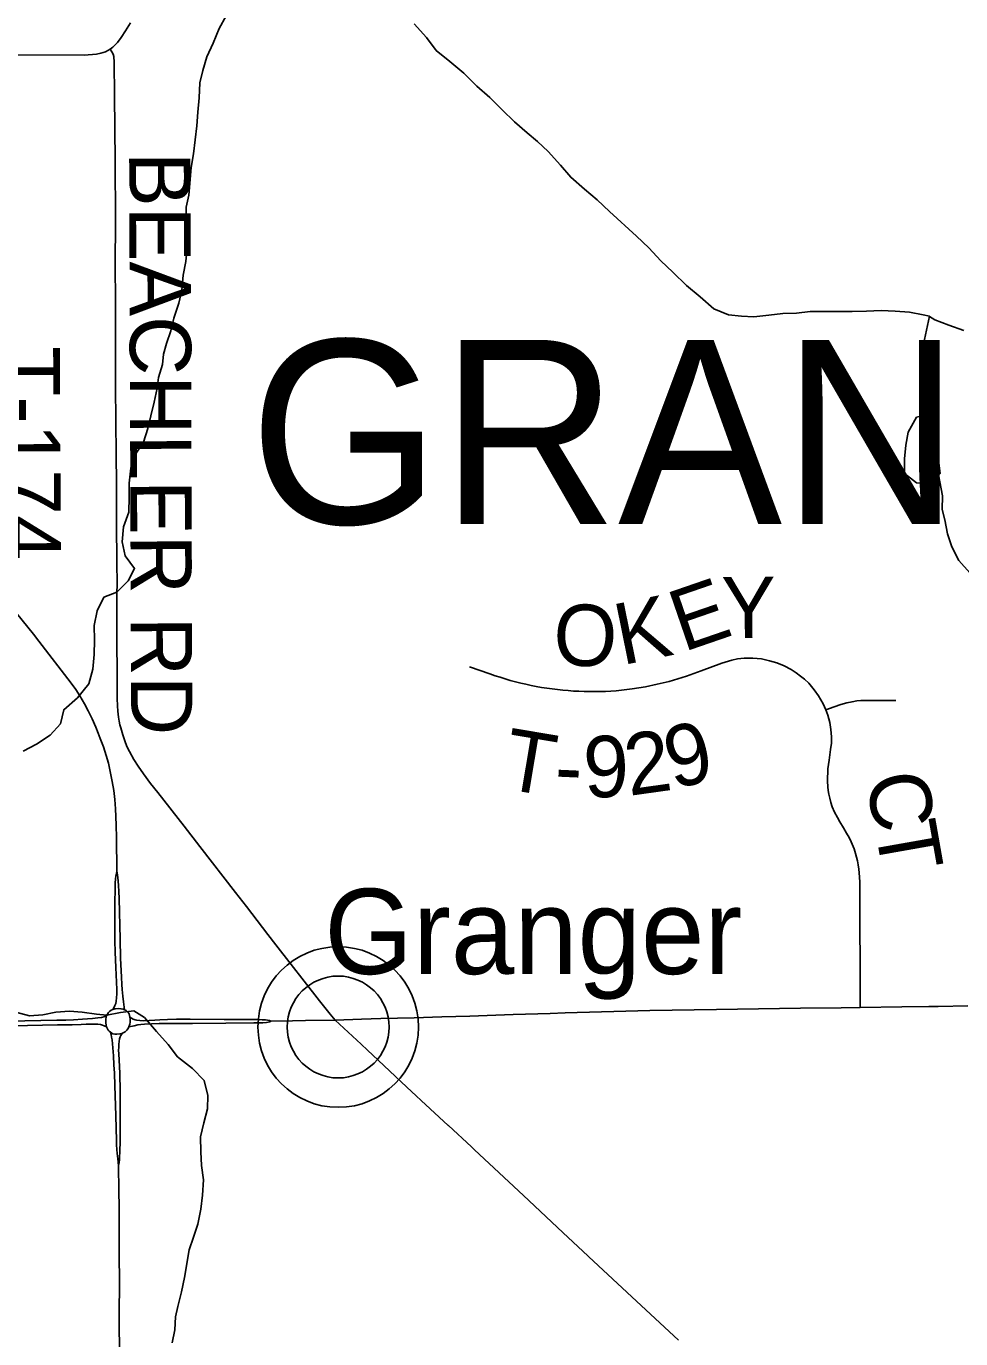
# Model space of a CAD drawing. Extents: x 0 to 34, y 0 to 22.
# Drawn here: x 5.327 to 6.193, y 15.589 to 16.805 of the extents above; entities that cross this region are included whole.
import ezdxf

# ---------------------------------------------------------------- set-up
doc = ezdxf.new("R2010")
doc.units = 0
for name, color, linetype in [('GM_X_County_Road', 7, 'Continuous'), ('GM_X_Minor_Lake', 7, 'Continuous'), ('GM_X_Minor_River', 7, 'Continuous'), ('GM_X_State_Route', 7, 'Continuous'), ('GM_X_Township_Road', 7, 'Continuous'), ('GM_X_Township_Road_Text', 7, 'Continuous'), ('GM_X_Township_Text', 7, 'Continuous'), ('GM_X_Unincorporated', 7, 'Continuous'), ('GM_X_Unincorporated_Location', 7, 'Continuous'), ('GM_X_Unincorporated_Text', 7, 'Continuous')]:
    doc.layers.add(name, color=color, linetype=linetype)

msp = doc.modelspace()

# ---------------------------------------------------------------- linework, layer by layer
at = {"layer": 'GM_X_County_Road'}
msp.add_line((5.5539, 15.8835), (5.574, 15.8838), dxfattribs=at)
for points in [[(5.4073, 15.8944), (5.4095, 15.895), (5.4122, 15.8952), (5.4149, 15.895), (5.4169, 15.8946), (5.4182, 15.8941)], [(5.574, 15.8838), (5.586, 15.884), (5.6136, 15.8845), (5.638, 15.8853), (5.6559, 15.886), (5.6867, 15.8866), (5.7123, 15.8874), (5.7385, 15.8882), (5.7786, 15.8896), (5.8129, 15.8907), (5.8268, 15.8911), (5.883, 15.8928), (5.9052, 15.8934), (5.967, 15.8943), (6.0449, 15.8955), (6.0827, 15.896), (6.1003, 15.8962), (6.139, 15.8967), (6.1639, 15.897), (6.1725, 15.8971), (6.2, 15.8976)], [(5.2717, 15.8801), (5.2732, 15.8808), (5.2758, 15.8817), (5.2782, 15.8822), (5.2804, 15.8825), (5.2853, 15.883), (5.292, 15.8833), (5.3259, 15.8838), (5.3555, 15.8843), (5.3639, 15.8845), (5.3708, 15.8848), (5.3794, 15.8853), (5.3885, 15.886), (5.3911, 15.8862), (5.3934, 15.8865), (5.3968, 15.887), (5.399, 15.8875), (5.4016, 15.8885)], [(5.4016, 15.8885), (5.4023, 15.8899), (5.4034, 15.8915), (5.4045, 15.8928), (5.4058, 15.8938), (5.4073, 15.8944)], [(5.4182, 15.8941), (5.4197, 15.8933), (5.4207, 15.8925), (5.4216, 15.8915), (5.4224, 15.8902), (5.4229, 15.8887), (5.4233, 15.8872)], [(5.4222, 15.8782), (5.4272, 15.8793), (5.4305, 15.88), (5.4334, 15.8804), (5.4368, 15.8807), (5.4431, 15.881), (5.4505, 15.8812), (5.4573, 15.8813), (5.4811, 15.8815), (5.5121, 15.8816), (5.5382, 15.8819), (5.5465, 15.882), (5.5497, 15.8823), (5.5515, 15.8827), (5.5529, 15.883), (5.5539, 15.8835)], [(5.4233, 15.8872), (5.4246, 15.8862), (5.4263, 15.8853), (5.428, 15.8847), (5.4296, 15.8843), (5.4324, 15.884), (5.4357, 15.8838), (5.441, 15.884), (5.4463, 15.8843), (5.4511, 15.8846), (5.458, 15.885), (5.4664, 15.8853), (5.4791, 15.8853), (5.5106, 15.8852), (5.5425, 15.885), (5.5459, 15.8848), (5.549, 15.8846), (5.5508, 15.8843), (5.5525, 15.884), (5.5539, 15.8835)], [(5.2717, 15.8801), (5.2748, 15.8795), (5.2778, 15.8791), (5.283, 15.8787), (5.2996, 15.8789), (5.3284, 15.8794), (5.3562, 15.88), (5.3697, 15.8801), (5.3779, 15.8804), (5.3826, 15.8806), (5.3883, 15.8807), (5.3935, 15.8806), (5.396, 15.8804), (5.3979, 15.8799), (5.3995, 15.8793), (5.4016, 15.8782)], [(5.4016, 15.8782), (5.4023, 15.8764), (5.4031, 15.8752), (5.4041, 15.8741), (5.4052, 15.8732)], [(5.4052, 15.8732), (5.4064, 15.8725), (5.4075, 15.8719), (5.4093, 15.8715), (5.411, 15.8714), (5.4138, 15.8717), (5.4151, 15.8719), (5.4171, 15.8726)], [(5.4171, 15.8726), (5.4187, 15.8736), (5.4203, 15.8751), (5.4215, 15.8766), (5.4222, 15.8782)]]:
    msp.add_lwpolyline(points, dxfattribs=at)
at = {"layer": 'GM_X_Minor_Lake'}
for points in [[(6.1627, 16.4455), (6.1526, 16.4431), (6.1446, 16.4294), (6.1427, 16.4172), (6.1412, 16.4046), (6.1412, 16.3909), (6.1523, 16.3822), (6.1621, 16.3816)], [(6.1626, 16.4455), (6.1526, 16.4431), (6.1446, 16.4294), (6.1427, 16.4172), (6.1412, 16.4046), (6.1412, 16.3909), (6.1523, 16.3822), (6.1621, 16.3816)], [(6.162, 16.3816), (6.1652, 16.3815), (6.1743, 16.391), (6.1732, 16.4005), (6.1732, 16.4134), (6.1728, 16.4267), (6.1712, 16.4397), (6.1626, 16.4456)], [(6.1621, 16.3816), (6.1652, 16.3815), (6.1743, 16.391), (6.1732, 16.4005), (6.1732, 16.4134), (6.1728, 16.4267), (6.1712, 16.4397), (6.1627, 16.4455)]]:
    msp.add_lwpolyline(points, dxfattribs=at)
at = {"layer": 'GM_X_Minor_River'}
for points in [[(5.5124, 16.8149), (5.506, 16.8032), (5.5003, 16.7898), (5.4946, 16.7769), (5.4908, 16.7643), (5.4882, 16.7529), (5.4874, 16.7389), (5.4863, 16.7259), (5.4852, 16.713), (5.4822, 16.6871), (5.4799, 16.6746), (5.4777, 16.6487), (5.4754, 16.6377), (5.475, 16.6259), (5.4754, 16.6137), (5.4762, 16.6), (5.4751, 16.5875), (5.4725, 16.5746), (5.4713, 16.5609), (5.4687, 16.5487), (5.4638, 16.535), (5.4611, 16.5232), (5.4573, 16.5114), (5.4543, 16.5015), (5.4535, 16.492), (5.4498, 16.4798), (5.4486, 16.47), (5.4456, 16.457), (5.4426, 16.4445), (5.4399, 16.4327), (5.4358, 16.4201), (5.4278, 16.4079), (5.424, 16.3958), (5.4225, 16.3821), (5.4225, 16.3691), (5.4222, 16.3551), (5.4172, 16.3414), (5.4161, 16.3277), (5.4188, 16.3148), (5.4276, 16.303), (5.4215, 16.2916), (5.4112, 16.2809), (5.3991, 16.2763), (5.393, 16.2638), (5.39, 16.2501), (5.3904, 16.2364), (5.39, 16.2234), (5.3889, 16.2098), (5.3851, 16.1961), (5.3745, 16.1831), (5.3619, 16.1721), (5.3589, 16.1591), (5.3494, 16.1485), (5.3365, 16.1401), (5.3243, 16.1336)], [(5.6867, 16.8076), (5.6981, 16.795), (5.7073, 16.7829), (5.7199, 16.7726), (5.7328, 16.762), (5.745, 16.7498), (5.7568, 16.7392), (5.7682, 16.7278), (5.7797, 16.7168), (5.7915, 16.7065), (5.801, 16.6986), (5.8109, 16.6894), (5.8223, 16.6765), (5.8319, 16.6655), (5.8448, 16.6545), (5.8563, 16.6446), (5.8677, 16.6336), (5.8928, 16.6108), (5.9043, 16.6002), (5.9153, 16.588), (5.9267, 16.5774), (5.9393, 16.5652), (5.9519, 16.5546), (5.9645, 16.5436), (5.9782, 16.5379), (5.9903, 16.5368), (6.0018, 16.536), (6.0155, 16.5376), (6.0284, 16.5391), (6.0413, 16.5395), (6.0539, 16.541), (6.0927, 16.5411), (6.106, 16.5415), (6.1197, 16.5419), (6.1326, 16.5415), (6.146, 16.5404), (6.1585, 16.5381)], [(6.1585, 16.5381), (6.1646, 16.5366), (6.1616, 16.5237), (6.1589, 16.5108), (6.159, 16.4978), (6.1582, 16.4849), (6.1632, 16.4727), (6.1659, 16.4606), (6.1667, 16.4428)], [(6.1645, 16.5365), (6.1696, 16.5332), (6.1825, 16.5283), (6.1962, 16.5234)], [(6.2019, 16.299), (6.1916, 16.3104), (6.1851, 16.3229), (6.1813, 16.3351), (6.1786, 16.348), (6.1763, 16.3575), (6.1766, 16.3704), (6.1729, 16.3896)], [(5.3175, 15.8917), (5.33, 15.8883), (5.3426, 15.8895), (5.3547, 15.8918), (5.3673, 15.8929), (5.3791, 15.8918), (5.3924, 15.8899), (5.4019, 15.8892), (5.4145, 15.8915), (5.427, 15.893)], [(5.427, 15.893), (5.4369, 15.8869), (5.448, 15.874), (5.4587, 15.8619), (5.4674, 15.8505), (5.4811, 15.8398), (5.4922, 15.8284), (5.4956, 15.8147), (5.4953, 15.8022), (5.4919, 15.7893), (5.4888, 15.7763), (5.4889, 15.7623), (5.4896, 15.7497), (5.4916, 15.7364), (5.4904, 15.7223), (5.4889, 15.7094), (5.4863, 15.6953), (5.4821, 15.6835), (5.4783, 15.6717), (5.4738, 15.6459), (5.4712, 15.6326), (5.4678, 15.6192), (5.4655, 15.6097), (5.4648, 15.5976), (5.4625, 15.5854)]]:
    msp.add_lwpolyline(points, dxfattribs=at)
at = {"layer": 'GM_X_State_Route'}
msp.add_line((5.4131, 15.7257), (5.4127, 15.7505), dxfattribs=at)
for points in [[(5.411, 16.0225), (5.4108, 16.0536), (5.4104, 16.0647), (5.4101, 16.073), (5.4098, 16.0803), (5.4091, 16.089), (5.4082, 16.0973), (5.4068, 16.1057), (5.405, 16.1149), (5.4033, 16.1227), (5.4013, 16.1297), (5.3987, 16.1376), (5.3958, 16.1453), (5.3939, 16.1503), (5.3916, 16.156), (5.3882, 16.1636), (5.3846, 16.1712), (5.381, 16.1776), (5.3768, 16.1849), (5.373, 16.1909), (5.3687, 16.1967), (5.3388, 16.2356), (5.3337, 16.242), (5.3062, 16.276)], [(5.4073, 15.8944), (5.4085, 15.8964), (5.4094, 15.898), (5.4101, 15.8998), (5.4106, 15.902), (5.4109, 15.905), (5.4111, 15.9089), (5.411, 15.9128), (5.4103, 15.9331), (5.4096, 15.9475), (5.4094, 15.9579), (5.4092, 15.9718), (5.4093, 15.9923), (5.4095, 16.007), (5.4097, 16.0116), (5.41, 16.0151), (5.4103, 16.0181), (5.4107, 16.0206), (5.411, 16.0225)], [(5.4182, 15.8941), (5.4173, 15.9014), (5.4166, 15.9068), (5.4161, 15.9129), (5.4157, 15.9176), (5.4153, 15.9242), (5.4146, 15.942), (5.4141, 15.9595), (5.4133, 15.9972), (5.4131, 16.0036), (5.4127, 16.0091), (5.4124, 16.0133), (5.4121, 16.0167), (5.4117, 16.0191), (5.4114, 16.0209), (5.411, 16.0225)], [(5.4016, 15.8782), (5.4011, 15.88), (5.4009, 15.8818), (5.4008, 15.8839), (5.401, 15.8855), (5.4012, 15.8871), (5.4016, 15.8885)], [(5.4016, 15.8885), (5.4023, 15.8899), (5.4034, 15.8915), (5.4045, 15.8928), (5.4058, 15.8938), (5.4073, 15.8944)], [(5.4233, 15.8872), (5.4229, 15.8887), (5.4224, 15.8902), (5.4216, 15.8915), (5.4207, 15.8925), (5.4197, 15.8933), (5.4182, 15.8941)], [(5.4222, 15.8782), (5.423, 15.8806), (5.4234, 15.8825), (5.4235, 15.8841), (5.4235, 15.8855), (5.4233, 15.8872)], [(5.4052, 15.8732), (5.4041, 15.8741), (5.4031, 15.8752), (5.4023, 15.8764), (5.4016, 15.8782)], [(5.4127, 15.7505), (5.4124, 15.7519), (5.4122, 15.7533), (5.4119, 15.756), (5.4114, 15.7609), (5.4111, 15.7647), (5.4109, 15.7688), (5.4107, 15.7728), (5.4101, 15.7958), (5.4093, 15.8239), (5.4089, 15.8353), (5.4084, 15.8432), (5.4079, 15.8513), (5.407, 15.8625), (5.4067, 15.8663), (5.4063, 15.8687), (5.4058, 15.8711), (5.4052, 15.8732)], [(5.4127, 15.7505), (5.4132, 15.7525), (5.4135, 15.7549), (5.4137, 15.7577), (5.4139, 15.762), (5.4141, 15.7728), (5.4143, 15.7889), (5.4143, 15.8045), (5.4143, 15.8133), (5.4141, 15.8238), (5.414, 15.8298), (5.4138, 15.8352), (5.4132, 15.8473), (5.4129, 15.8533), (5.4128, 15.8565), (5.4129, 15.8592), (5.413, 15.8621), (5.4133, 15.8648), (5.4137, 15.867), (5.4143, 15.8689), (5.4149, 15.8701), (5.4158, 15.8714), (5.4171, 15.8726)], [(5.4171, 15.8726), (5.4187, 15.8736), (5.4203, 15.8751), (5.4215, 15.8766), (5.4222, 15.8782)], [(5.4137, 15.569), (5.4134, 15.6126), (5.4136, 15.6406), (5.4134, 15.6681), (5.4132, 15.7117), (5.4131, 15.7257)]]:
    msp.add_lwpolyline(points, dxfattribs=at)
at = {"layer": 'GM_X_Township_Road'}
for points in [[(5.3115, 16.7788), (5.3807, 16.7787), (5.3922, 16.7794), (5.3963, 16.7803), (5.4006, 16.7818), (5.4048, 16.784), (5.4074, 16.786), (5.4099, 16.7883), (5.4117, 16.7903), (5.4152, 16.795), (5.4192, 16.8012), (5.4237, 16.8085)], [(5.4112, 16.2813), (5.4113, 16.2872), (5.4112, 16.3101), (5.4109, 16.3432), (5.4107, 16.382), (5.4104, 16.4082), (5.41, 16.4712), (5.4099, 16.5226), (5.4098, 16.5522), (5.4097, 16.5824), (5.4099, 16.6261), (5.4096, 16.6804), (5.4089, 16.7413), (5.4086, 16.7722), (5.4083, 16.7773), (5.4078, 16.7796), (5.4066, 16.7816), (5.4048, 16.784)], [(5.4115, 16.1824), (5.4112, 16.2588), (5.4112, 16.2813)], [(6.1003, 15.8962), (6.0999, 16.0119), (6.0997, 16.0174), (6.099, 16.0245), (6.0985, 16.0285), (6.0978, 16.0322), (6.096, 16.0388), (6.0946, 16.0431), (6.0918, 16.0497), (6.0899, 16.0538), (6.0877, 16.0576), (6.0847, 16.0628), (6.0815, 16.0683), (6.0792, 16.0721), (6.0765, 16.0771), (6.0744, 16.082), (6.0731, 16.0862), (6.0721, 16.09), (6.0712, 16.0939), (6.0705, 16.0973), (6.0701, 16.1007), (6.0698, 16.1058), (6.0701, 16.1172), (6.0714, 16.1254), (6.0728, 16.1351), (6.0735, 16.1412), (6.0736, 16.147), (6.073, 16.1537), (6.0721, 16.1601), (6.0703, 16.1669), (6.0685, 16.1721), (6.066, 16.1775), (6.0616, 16.1849), (6.0577, 16.1906), (6.0526, 16.1967), (6.0485, 16.2005), (6.045, 16.2032), (6.041, 16.2063), (6.0363, 16.2094), (6.0297, 16.2128), (6.0231, 16.2154), (6.0163, 16.2175), (6.0088, 16.2191), (6.0007, 16.2198), (5.9927, 16.2199), (5.9864, 16.2192), (5.9812, 16.218), (5.972, 16.2152), (5.9529, 16.208), (5.946, 16.2056), (5.9391, 16.2032), (5.9313, 16.2006), (5.9232, 16.1983), (5.9119, 16.1957), (5.9011, 16.1934), (5.8888, 16.1913), (5.8839, 16.1907), (5.879, 16.1901), (5.874, 16.1897), (5.8691, 16.1894), (5.8641, 16.1891), (5.8592, 16.189), (5.8542, 16.1889), (5.8443, 16.189), (5.8394, 16.1892), (5.8344, 16.1894), (5.8295, 16.1898), (5.8245, 16.1902), (5.8196, 16.1908), (5.8147, 16.1914), (5.8098, 16.1921), (5.8049, 16.1928), (5.8, 16.1937), (5.7952, 16.1946), (5.7903, 16.1957), (5.7855, 16.1968), (5.7807, 16.198), (5.7759, 16.1993), (5.7712, 16.2007), (5.7664, 16.2021), (5.7617, 16.2036), (5.757, 16.2053), (5.7382, 16.2119)], [(5.6136, 15.8845), (5.6088, 15.8899), (5.5989, 15.9023), (5.5585, 15.9543), (5.5512, 15.9638), (5.5314, 15.9897), (5.5211, 16.0027), (5.4882, 16.0454), (5.4736, 16.0642), (5.4491, 16.0954), (5.4424, 16.1038), (5.4358, 16.1128), (5.431, 16.1198), (5.427, 16.126), (5.4228, 16.1333), (5.4208, 16.1374), (5.4192, 16.1413), (5.4166, 16.1488), (5.4147, 16.1554), (5.414, 16.1581), (5.4132, 16.1615), (5.4126, 16.1652), (5.412, 16.1708), (5.4117, 16.1758), (5.4115, 16.1824)], [(6.0685, 16.1721), (6.076, 16.1747), (6.0824, 16.1769), (6.0879, 16.1784), (6.0927, 16.1795), (6.097, 16.1802), (6.101, 16.1805), (6.1057, 16.1806), (6.1332, 16.1806)], [(5.9317, 15.588), (5.8929, 15.624), (5.8486, 15.6652), (5.848, 15.6657), (5.8247, 15.6876), (5.788, 15.7219), (5.7427, 15.7644), (5.7398, 15.767), (5.7185, 15.7868), (5.7182, 15.7869), (5.6933, 15.8101), (5.6887, 15.8144), (5.6801, 15.8224), (5.6534, 15.8473), (5.6436, 15.8567), (5.6376, 15.8622), (5.6136, 15.8845)]]:
    msp.add_lwpolyline(points, dxfattribs=at)
at = {"layer": 'GM_X_Unincorporated'}
for radius in [0.0744, 0.0472]:
    msp.add_circle((5.6163, 15.8781), radius, dxfattribs=at)
at = {"layer": 'GM_X_Unincorporated_Location'}
msp.add_line((5.6163, 15.8781), (5.6163, 15.8781), dxfattribs=at)

# ---------------------------------------------------------------- texts
at = {"layer": 'GM_X_Township_Road_Text'}
for s, height, rotation, p in [('BEACHLER RD', 0.056818, 270.1993, (5.4225, 16.6888)), ('T-174', 0.05682, 270.2797, (5.3015, 16.5088)), ('E', 0.0568, 19.0093, (5.9362, 16.2253)), ('Y', 0.0568, 0.4554, (5.9716, 16.2383)), ('K', 0.0568, 11.4466, (5.8793, 16.2132)), ('O', 0.0568, 358.335, (5.8152, 16.2135)), ('T', 0.0568, 350.4158, (5.7669, 16.0994)), ('2', 0.0568, 7.9586, (5.8859, 16.0922)), ('9', 0.0568, 13.6599, (5.9267, 16.0982)), ('9', 0.0568, 1.9576, (5.8445, 16.0904)), ('-', 0.0568, 357.4728, (5.8163, 16.0915)), ('C', 0.0568, 281.2778, (6.1046, 16.1091)), ('T', 0.0568, 280.0408, (6.1136, 16.0637))]:
    msp.add_text(s, height=height, rotation=rotation, dxfattribs=at).set_placement(p)
at = {"layer": 'GM_X_Township_Text'}
msp.add_text('GRANGER', height=0.17045, rotation=0, dxfattribs=at).set_placement((5.5339, 16.3443))
at = {"layer": 'GM_X_Unincorporated_Text'}
msp.add_text('Granger', height=0.07898, rotation=0, dxfattribs=at).set_placement((5.6035, 15.9272))

doc.saveas('drawing.dxf')
